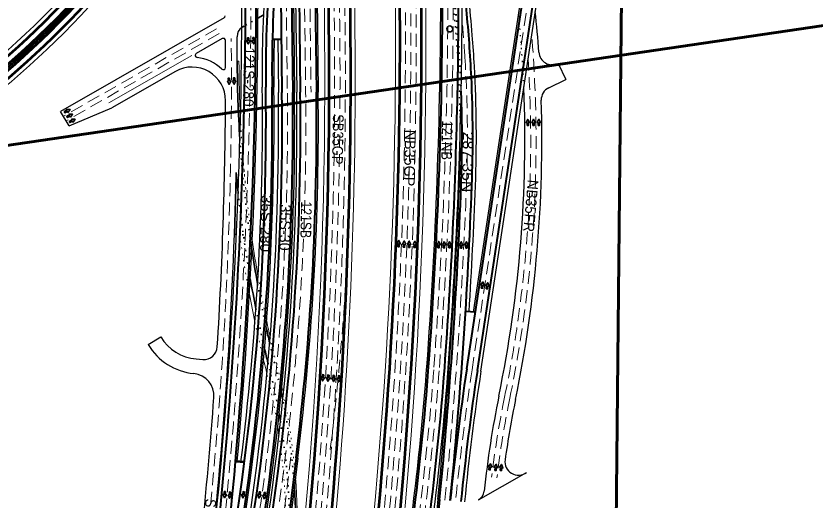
# Model space of a CAD drawing. Extents: x 2329387 to 2347382, y 6951580 to 6987999.
# Drawn here: x 2331270 to 2333058, y 6962627 to 6963710 of the extents above; entities that cross this region are included whole.
import ezdxf

# ---------------------------------------------------------------- set-up
doc = ezdxf.new("R2010")
doc.units = 0
doc.header["$LTSCALE"] = 9.6
doc.linetypes.add('DOTTED', pattern=[1.5, 0.3, -1.2])
doc.linetypes.add('MEDIUM_DASHED', pattern=[4.5, 3, -1.5])
for name, color, linetype, lineweight in [('26', 7, 'Continuous', 53), ('27', 7, 'Continuous', 40), ('28', 7, 'Continuous', 25), ('29', 7, 'DOTTED', 35), ('31', 7, 'Continuous', 53), ('41', 7, 'Continuous', 35), ('50', 7, 'MEDIUM_DASHED', 13), ('62', 7, 'Continuous', 60)]:
    doc.layers.add(name, color=color, linetype=linetype, lineweight=lineweight)
doc.layers.add('40', color=7, linetype='Continuous')

msp = doc.modelspace()

# ---------------------------------------------------------------- linework, layer by layer
at = {"layer": '26'}
for centre, radius, start, end in [((2320619.05, 6963651.709), 11510.156, 348.37024, 3.41668), ((2321018.843, 6963569.511), 11000, 348.37024, 2.99621), ((2320619.05, 6963651.709), 11558.156, 353.8091, 2.18285), ((2321018.843, 6963569.511), 10952, 352.02498, 2.27299)]:
    msp.add_arc(centre, radius, start, end, dxfattribs=at)
at = {"layer": '26', "lineweight": 13}
for centre, radius, start, end in [((2320619.05, 6963651.709), 11500.156, 348.37024, 3.35435), ((2321018.843, 6963569.511), 11010, 348.37024, 3.10741), ((2320619.05, 6963651.709), 11568.156, 353.8091, 2.18285), ((2321018.843, 6963569.511), 10942, 352.02498, 2.03298)]:
    msp.add_arc(centre, radius, start, end, dxfattribs=at)
at = {"layer": '27'}
for p, q in [((2331859.891, 6963964.924), (2331864.989, 6963538.523)), ((2331883.889, 6963965.211), (2331888.987, 6963538.81)), ((2331902.724, 6963811.829), (2331905.986, 6963539.014)), ((2331938.722, 6963812.26), (2331941.983, 6963539.444)), ((2332278.43, 6962920.203), (2332404.465, 6963752.658)), ((2332302.159, 6962916.61), (2332428.993, 6963754.341)), ((2331843.561, 6963657.847), (2331863.559, 6963658.086)), ((2332297.639, 6963047.078), (2332275.682, 6963048.447)), ((2331896.517, 6962721.31), (2331783.536, 6961807.284))]:
    msp.add_line(p, q, dxfattribs=at)
at = {"layer": '27', "lineweight": 25}
for p, q in [((2331887.889, 6963965.259), (2331892.986, 6963538.858)), ((2331894.725, 6963811.734), (2331897.986, 6963538.918)), ((2331942.721, 6963812.307), (2331945.983, 6963539.492)), ((2332293.631, 6963047.328), (2332400.51, 6963753.257)), ((2332310.069, 6962915.412), (2332436.903, 6963753.144)), ((2331855.56, 6963657.991), (2331856.989, 6963538.428)), ((2331900.487, 6962720.82), (2331787.506, 6961806.793))]:
    msp.add_line(p, q, dxfattribs=at)
at = {"layer": '27', "lineweight": 53}
msp.add_line((2331781.036, 6962711.686), (2331761.113, 6962713.441), dxfattribs=at)
at = {"layer": '27'}
for centre, radius, start, end in [((2339406.145, 6959556.474), 7976, 170.51466, 170.51466), ((2319783.502, 6963768.598), 11999.998, 350.71583, 0.79832), ((2319783.502, 6963768.598), 12023.998, 353.14789, 0.79832), ((2334658.491, 6963585.255), 2829.866, 175.42223, 180.70842), ((2334658.491, 6963585.255), 2815.866, 175.42223, 180.70842), ((2329427.098, 6963438.985), 2864.789, 4.18795, 7.21791), ((2320644.096, 6963773.403), 11580.156, 355.79715, 359.92799), ((2320644.096, 6963773.403), 11616.156, 358.83349, 359.92799), ((2329427.098, 6963438.985), 2864.789, 2.67871, 4.18794), ((2329427.098, 6963438.985), 2864.789, 357.81948, 2.67871), ((2325765.131, 6963475.29), 6064.174, 349.61744, 0.70842), ((2325765.131, 6963475.29), 6078.174, 349.61744, 0.70842), ((2325865.417, 6963466.803), 6000, 350.51466, 0.68489), ((2325865.417, 6963466.803), 6024, 350.51466, 0.68489), ((2325865.417, 6963466.803), 6041, 350.76507, 0.68489), ((2325865.417, 6963466.803), 6077, 352.95352, 0.6849), ((2320644.096, 6963773.403), 11616.156, 355.79988, 358.83349), ((2329427.098, 6963438.985), 2840.789, 357.81948, 2.00707), ((2320644.096, 6963773.403), 11630.156, 354.34987, 357.81948), ((2320644.096, 6963773.403), 11654.156, 354.34987, 357.81948), ((2326209.306, 6963364.708), 5999.959, 349.28886, 355.79988), ((2326209.306, 6963364.708), 6035.959, 349.28886, 355.79988), ((2337955.315, 6962060.73), 5741.578, 171.39088, 174.34987), ((2337955.315, 6962060.73), 5717.578, 171.39088, 174.34987), ((2337955.315, 6962060.73), 5765.578, 174.34987, 182.32731)]:
    msp.add_arc(centre, radius, start, end, dxfattribs=at)
at = {"layer": '27', "lineweight": 25}
for centre, radius, start, end in [((2319783.502, 6963768.598), 11991.998, 350.71583, 0.79832), ((2319783.502, 6963768.598), 12027.998, 354.96558, 0.79832), ((2329427.098, 6963438.985), 2872.789, 4.547, 7.97211), ((2334658.491, 6963585.255), 2837.866, 175.42223, 180.70842), ((2320644.096, 6963773.403), 11576.156, 355.79715, 359.94511), ((2320644.096, 6963773.403), 11624.156, 359.20212, 359.92799), ((2334658.491, 6963585.255), 2811.866, 178.51968, 180.70842), ((2329427.098, 6963438.985), 2872.789, 3.16532, 4.54699), ((2320644.096, 6963773.403), 11624.156, 355.79988, 359.20212), ((2329427.098, 6963438.985), 2872.789, 357.81948, 3.16532), ((2325765.131, 6963475.29), 6082.174, 349.61744, 0.70842), ((2325765.131, 6963475.29), 6056.174, 352.76318, 0.70842), ((2325865.417, 6963466.803), 5992, 350.51466, 0.68489), ((2325865.417, 6963466.803), 6028, 350.51466, 0.68489), ((2325865.417, 6963466.803), 6033, 350.76507, 0.68489), ((2325865.417, 6963466.803), 6081, 352.95352, 0.6849), ((2329427.098, 6963438.985), 2836.789, 357.81948, 0.29401), ((2320644.096, 6963773.403), 11626.156, 354.34987, 357.81948), ((2320644.096, 6963773.403), 11662.156, 356.43357, 357.81948), ((2326209.306, 6963364.708), 5995.959, 350.77341, 355.79988), ((2326209.306, 6963364.708), 6043.959, 349.28886, 355.79988), ((2337955.315, 6962060.73), 5709.578, 171.39088, 174.34987), ((2337955.315, 6962060.73), 5769.578, 174.34987, 182.32731)]:
    msp.add_arc(centre, radius, start, end, dxfattribs=at)
at = {"layer": '27', "linetype": 'DOTTED'}
msp.add_arc((2329427.098, 6963438.985), 2840.789, 2.00707, 9.24389, dxfattribs=at)
at = {"layer": '27', "linetype": 'DOTTED', "lineweight": 25}
msp.add_arc((2329427.098, 6963438.985), 2836.789, 0.29402, 8.98982, dxfattribs=at)
at = {"layer": '28', "lineweight": 35}
msp.add_line((2331823.249, 6963711.573), (2331811.33, 6963704.776), dxfattribs=at)
at = {"layer": '28'}
for p, q in [((2331735.388, 6963705.212), (2331369.146, 6963496.347)), ((2331731.057, 6963658.997), (2331673.353, 6963626.089)), ((2332482.628, 6963603.48), (2332500.38, 6963567.633)), ((2331626.602, 6963585.613), (2331484.263, 6963504.438)), ((2332462.047, 6963549.162), (2332500.38, 6963567.633)), ((2331388.592, 6963463.692), (2331369.146, 6963496.347)), ((2331388.592, 6963463.692), (2331484.263, 6963504.438)), ((2331565.734, 6962975.098), (2331594.215, 6962991.766)), ((2331672.99, 6962942.56), (2331688.11, 6962941.418)), ((2332304.35, 6962627.635), (2332411.916, 6962688.785))]:
    msp.add_line(p, q, dxfattribs=at)
at = {"layer": '28', "linetype": 'DOTTED', "lineweight": 35}
msp.add_line((2331811.33, 6963704.776), (2331780.207, 6963687.027), dxfattribs=at)
at = {"layer": '28', "lineweight": 13}
msp.add_line((2331764.819, 6963608.628), (2331768.819, 6963608.644), dxfattribs=at)
at = {"layer": '28'}
for centre, radius, start, end in [((2331732.911, 6963709.555), 5, 299.69572, 0.81201), ((2329579.73, 6963430.486), 2866.789, 3.95936, 5.79437), ((2331789.457, 6963663.522), 25, 124.76483, 180.53847), ((2331733.534, 6963654.653), 5, 0.48946, 119.69572), ((2321980.757, 6963571.336), 9784.134, 0.21838, 0.53847), ((2321980.757, 6963571.336), 9758.134, 0.13638, 0.48946), ((2331675.83, 6963621.745), 5, 119.69572, 263.20196), ((2332469.606, 6963630.507), 30, 183.95936, 295.72664), ((2331663.756, 6963520.463), 97, 46.58215, 83.20195), ((2334629.587, 6963619.547), 2864.789, 180.21838, 183.71741), ((2331663.756, 6963520.463), 75, 359.69898, 119.69572), ((2331733.862, 6963594.551), 5, 226.58215, 0.13638), ((2329579.73, 6963430.486), 2828.789, 348.36088, 2.40537), ((2332475.069, 6963522.136), 30, 115.72664, 181.81305), ((2321980.757, 6963571.336), 9758.134, 356.46392, 359.69898), ((2329579.73, 6963430.486), 2866.789, 348.36088, 1.81305), ((2321980.757, 6963571.336), 9784.134, 352.54246, 357.94854), ((2331680.521, 6963042.276), 100, 210.33806, 265.68072), ((2331680.521, 6963042.276), 133, 210.33806, 264.44438), ((2331690.369, 6962971.333), 30, 265.68072, 356.46392), ((2331662.804, 6962860.136), 50, 355.79885, 84.44438), ((2321980.757, 6963571.336), 9758.134, 352.45851, 355.79885), ((2334455.922, 6962426.078), 2149.773, 168.36088, 174.09796), ((2334455.922, 6962426.078), 2111.773, 168.36088, 172.08227), ((2332393.995, 6962712.845), 30, 172.08227, 306.68141), ((2332292.681, 6962649.744), 25, 297.82484, 354.00801)]:
    msp.add_arc(centre, radius, start, end, dxfattribs=at)
at = {"layer": '28', "linetype": 'DOTTED'}
for centre, radius, start, end in [((2329579.73, 6963430.486), 2828.789, 2.40537, 5.72863), ((2334629.587, 6963619.547), 2864.789, 183.71741, 185.54829)]:
    msp.add_arc(centre, radius, start, end, dxfattribs=at)
at = {"layer": '28', "lineweight": 13}
for centre, radius, start, end in [((2334629.587, 6963619.547), 2860.789, 180.21835, 182.74682), ((2334629.587, 6963619.547), 2860.789, 188.25774, 189.89333), ((2334629.587, 6963619.547), 2886.789, 190.61635, 191.87502), ((2334629.587, 6963619.547), 2860.789, 191.94861, 192.67825), ((2334629.587, 6963619.547), 2886.789, 193.6017, 194.06553), ((2330382.082, 6962555.363), 1491.999, 13.73046, 14.06553), ((2330382.082, 6962555.363), 1517.999, 11.74962, 12.3699), ((2330382.082, 6962555.363), 1491.999, 8.34815, 9.07887), ((2330382.082, 6962555.363), 1517.999, 353.8183, 4.62003)]:
    msp.add_arc(centre, radius, start, end, dxfattribs=at)
at = {"layer": '28', "linetype": 'DOTTED', "lineweight": 13}
for centre, radius, start, end in [((2334629.587, 6963619.547), 2860.789, 182.74682, 188.25774), ((2334629.587, 6963619.547), 2886.789, 187.94221, 190.61635), ((2334629.587, 6963619.547), 2860.789, 189.89333, 191.94861), ((2334629.587, 6963619.547), 2886.789, 191.87502, 193.6017), ((2334629.587, 6963619.547), 2860.789, 192.67825, 194.06553), ((2330382.082, 6962555.363), 1517.999, 12.3699, 14.06553), ((2330382.082, 6962555.363), 1491.999, 9.07887, 13.73046), ((2330382.082, 6962555.363), 1517.999, 4.62003, 11.74962), ((2330382.082, 6962555.363), 1491.999, 357.81169, 8.34815)]:
    msp.add_arc(centre, radius, start, end, dxfattribs=at)
at = {"layer": '29'}
for p, q in [((2331780.207, 6963687.027), (2331777.072, 6963685.239)), ((2331778.607, 6963220.376), (2331762.988, 6963220.936))]:
    msp.add_line(p, q, dxfattribs=at)
at = {"layer": '29', "linetype": 'Continuous'}
msp.add_line((2331762.988, 6963220.936), (2331758.619, 6963221.092), dxfattribs=at)
at = {"layer": '29'}
for centre, radius, start, end in [((2331789.457, 6963663.522), 25, 119.69572, 124.76483), ((2334629.587, 6963619.547), 2864.789, 183.71739, 188.66291), ((2334629.587, 6963619.547), 2878.789, 186.06786, 189.95134), ((2334629.587, 6963619.547), 2864.789, 190.22859, 192.21722), ((2334629.587, 6963619.547), 2878.789, 191.3098, 193.12052), ((2334629.587, 6963619.547), 2864.789, 192.93344, 194.06553), ((2334629.587, 6963619.547), 2878.789, 193.78065, 194.06553), ((2330382.082, 6962555.363), 1513.999, 11.89833, 14.06553), ((2330382.082, 6962555.363), 1499.999, 10.15303, 14.06553), ((2330382.082, 6962555.363), 1513.999, 3.86264, 11.26427), ((2330382.082, 6962555.363), 1499.999, 0.60632, 9.46235)]:
    msp.add_arc(centre, radius, start, end, dxfattribs=at)
at = {"layer": '29', "linetype": 'Continuous'}
for centre, radius, start, end in [((2334629.587, 6963619.547), 2864.789, 180.21835, 183.71739), ((2321980.757, 6963571.336), 9784.134, 357.94854, 358.75788), ((2334629.587, 6963619.547), 2878.789, 185.18787, 185.29222), ((2334629.587, 6963619.547), 2878.789, 185.18786, 186.06786), ((2334629.587, 6963619.547), 2864.789, 188.66292, 190.22859), ((2334629.587, 6963619.547), 2878.789, 189.95135, 191.3098), ((2334629.587, 6963619.547), 2864.789, 192.21722, 192.93344), ((2334629.587, 6963619.547), 2878.789, 193.12052, 193.78065), ((2330382.082, 6962555.363), 1513.999, 11.26427, 11.89833), ((2330382.082, 6962555.363), 1499.999, 9.46235, 10.15303), ((2330382.082, 6962555.363), 1513.999, 353.8183, 3.86264)]:
    msp.add_arc(centre, radius, start, end, dxfattribs=at)
at = {"layer": '31', "lineweight": 13}
for radius, end in [(2054.483, 348.49858), (2082.483, 347.70072), (2084.483, 347.64774), (2112.483, 346.95514)]:
    msp.add_arc((2329883.662, 6965166.203), radius, 300.39505, end, dxfattribs=at)
at = {"layer": '31'}
for radius, end in [(2064.483, 348.20098), (2078.483, 347.80819), (2088.483, 347.54327), (2102.483, 347.19243)]:
    msp.add_arc((2329883.662, 6965166.203), radius, 300.39505, end, dxfattribs=at)
at = {"layer": '41'}
for points in [[(2331790.891, 6963661.054), (2331787.892, 6963660.956), (2331788.114, 6963654.153), (2331785.678, 6963654.074), (2331789.69, 6963647.001), (2331793.232, 6963654.32), (2331791.113, 6963654.251)], [(2331803.026, 6963661.337), (2331800.027, 6963661.239), (2331800.249, 6963654.436), (2331797.813, 6963654.356), (2331801.825, 6963647.283), (2331805.367, 6963654.603), (2331803.248, 6963654.534)], [(2331747.951, 6963570.808), (2331744.951, 6963570.71), (2331745.174, 6963563.907), (2331742.737, 6963563.827), (2331746.749, 6963556.754), (2331750.291, 6963564.074), (2331748.173, 6963564.004)], [(2331759.264, 6963571.071), (2331756.265, 6963570.973), (2331756.487, 6963564.17), (2331754.051, 6963564.091), (2331758.062, 6963557.018), (2331761.604, 6963564.337), (2331759.486, 6963564.268)], [(2331377.597, 6963496.027), (2331378.906, 6963493.327), (2331385.031, 6963496.296), (2331386.095, 6963494.103), (2331390.925, 6963500.645), (2331382.797, 6963500.904), (2331383.722, 6963498.996)], [(2331383.314, 6963485.285), (2331384.623, 6963482.585), (2331390.748, 6963485.555), (2331391.811, 6963483.361), (2331396.641, 6963489.903), (2331388.514, 6963490.162), (2331389.438, 6963488.255)], [(2331388.918, 6963473.904), (2331390.227, 6963471.204), (2331396.352, 6963474.174), (2331397.415, 6963471.98), (2331402.245, 6963478.522), (2331394.118, 6963478.781), (2331395.042, 6963476.874)], [(2332413.321, 6963464.425), (2332416.321, 6963464.431), (2332416.307, 6963471.238), (2332418.744, 6963471.243), (2332414.95, 6963478.435), (2332411.187, 6963471.227), (2332413.306, 6963471.232)], [(2332426.006, 6963464.529), (2332429.007, 6963464.535), (2332428.992, 6963471.342), (2332431.43, 6963471.347), (2332427.636, 6963478.539), (2332423.872, 6963471.331), (2332425.992, 6963471.335)], [(2332438.224, 6963464.729), (2332441.225, 6963464.736), (2332441.211, 6963471.542), (2332443.648, 6963471.548), (2332439.854, 6963478.74), (2332436.09, 6963471.532), (2332438.21, 6963471.536)], [(2332124.457, 6963193.624), (2332127.456, 6963193.541), (2332127.646, 6963200.345), (2332130.082, 6963200.277), (2332126.505, 6963207.58), (2332122.527, 6963200.487), (2332124.646, 6963200.428)], [(2332136.489, 6963192.561), (2332139.488, 6963192.477), (2332139.678, 6963199.281), (2332142.114, 6963199.214), (2332138.537, 6963206.516), (2332134.559, 6963199.424), (2332136.678, 6963199.365)], [(2332147.797, 6963192.14), (2332150.797, 6963192.057), (2332150.986, 6963198.861), (2332153.423, 6963198.793), (2332149.845, 6963206.096), (2332145.868, 6963199.003), (2332147.987, 6963198.945)], [(2332160.367, 6963191.834), (2332163.367, 6963191.751), (2332163.556, 6963198.555), (2332165.992, 6963198.487), (2332162.415, 6963205.789), (2332158.438, 6963198.697), (2332160.556, 6963198.638)], [(2332213.987, 6963191.388), (2332216.988, 6963191.374), (2332217.019, 6963198.181), (2332219.456, 6963198.169), (2332215.711, 6963205.387), (2332211.899, 6963198.204), (2332214.018, 6963198.194)], [(2332225.968, 6963190.81), (2332228.969, 6963190.796), (2332229, 6963197.602), (2332231.438, 6963197.591), (2332227.692, 6963204.809), (2332223.88, 6963197.626), (2332226, 6963197.616)], [(2332238.106, 6963190.864), (2332241.107, 6963190.85), (2332241.138, 6963197.657), (2332243.575, 6963197.645), (2332239.83, 6963204.863), (2332236.018, 6963197.68), (2332238.137, 6963197.67)], [(2332264.212, 6963190.637), (2332267.213, 6963190.623), (2332267.244, 6963197.43), (2332269.682, 6963197.418), (2332265.936, 6963204.636), (2332262.124, 6963197.453), (2332264.244, 6963197.444)], [(2332276.35, 6963190.691), (2332279.35, 6963190.677), (2332279.382, 6963197.484), (2332281.819, 6963197.472), (2332278.074, 6963204.69), (2332274.262, 6963197.507), (2332276.381, 6963197.498)], [(2332310.718, 6963101.297), (2332313.677, 6963100.798), (2332314.81, 6963107.509), (2332317.213, 6963107.104), (2332314.685, 6963114.832), (2332309.761, 6963108.361), (2332311.851, 6963108.009)], [(2332321.516, 6963099.46), (2332324.475, 6963098.961), (2332325.607, 6963105.672), (2332328.011, 6963105.267), (2332325.483, 6963112.995), (2332320.559, 6963106.524), (2332322.648, 6963106.172)], [(2331958.338, 6962907.47), (2331955.341, 6962907.621), (2331954.998, 6962900.823), (2331952.564, 6962900.946), (2331955.975, 6962893.564), (2331960.112, 6962900.565), (2331957.995, 6962900.672)], [(2331970.315, 6962906.73), (2331967.318, 6962906.881), (2331966.975, 6962900.083), (2331964.541, 6962900.205), (2331967.952, 6962892.824), (2331972.089, 6962899.825), (2331969.972, 6962899.932)], [(2331982.292, 6962905.989), (2331979.295, 6962906.141), (2331978.952, 6962899.342), (2331976.518, 6962899.465), (2331979.93, 6962892.084), (2331984.066, 6962899.085), (2331981.949, 6962899.191)], [(2331994.269, 6962905.249), (2331991.272, 6962905.4), (2331990.93, 6962898.602), (2331988.495, 6962898.725), (2331991.907, 6962891.344), (2331996.043, 6962898.344), (2331993.927, 6962898.451)], [(2332328.001, 6962694.82), (2332330.972, 6962694.405), (2332331.915, 6962701.146), (2332334.328, 6962700.809), (2332331.583, 6962708.463), (2332326.844, 6962701.855), (2332328.943, 6962701.562)], [(2332340.907, 6962693.485), (2332343.879, 6962693.069), (2332344.821, 6962699.811), (2332347.235, 6962699.473), (2332344.489, 6962707.127), (2332339.75, 6962700.519), (2332341.85, 6962700.226)], [(2332352.924, 6962693.04), (2332355.896, 6962692.624), (2332356.838, 6962699.365), (2332359.252, 6962699.028), (2332356.506, 6962706.682), (2332351.767, 6962700.074), (2332353.866, 6962699.781)], [(2331738.885, 6962645.963), (2331735.891, 6962646.163), (2331735.438, 6962639.372), (2331733.006, 6962639.534), (2331736.296, 6962632.098), (2331740.546, 6962639.03), (2331738.432, 6962639.171)], [(2331750.52, 6962644.951), (2331747.526, 6962645.151), (2331747.072, 6962638.36), (2331744.64, 6962638.522), (2331747.93, 6962631.086), (2331752.181, 6962638.018), (2331750.066, 6962638.159)], [(2331780.891, 6962645.715), (2331777.915, 6962646.098), (2331777.046, 6962639.347), (2331774.629, 6962639.658), (2331777.457, 6962632.035), (2331782.125, 6962638.694), (2331780.022, 6962638.964)], [(2331816.978, 6962645.27), (2331814.002, 6962645.654), (2331813.132, 6962638.903), (2331810.715, 6962639.215), (2331813.542, 6962631.591), (2331818.211, 6962638.249), (2331816.108, 6962638.52)], [(2331828.386, 6962643.649), (2331825.41, 6962644.032), (2331824.54, 6962637.281), (2331822.123, 6962637.593), (2331824.95, 6962629.969), (2331829.618, 6962636.627), (2331827.516, 6962636.898)]]:
    msp.add_lwpolyline(points, close=True, dxfattribs=at)
at = {"layer": '50'}
for p, q in [((2331871.89, 6963965.067), (2331876.988, 6963538.667)), ((2331914.723, 6963811.973), (2331917.985, 6963539.157)), ((2331926.723, 6963812.116), (2331929.984, 6963539.301)), ((2332290.295, 6962918.406), (2332416.33, 6963750.862)), ((2331718.672, 6963680.714), (2331376.207, 6963485.409)), ((2331724.617, 6963670.29), (2331382.152, 6963474.985)), ((2331884.608, 6962722.782), (2331771.627, 6961808.756))]:
    msp.add_line(p, q, dxfattribs=at)
at = {"layer": '50', "linetype": 'Continuous'}
msp.add_line((2331663.342, 6963621.53), (2331477.823, 6963515.731), dxfattribs=at)
at = {"layer": '50', "linetype": 'DOTTED'}
msp.add_line((2331780.994, 6963355.668), (2331786.908, 6963291.834), dxfattribs=at)
at = {"layer": '50', "linetype": 'Continuous', "lineweight": 35}
msp.add_circle((2332240.47, 6963680.652), 6.657, dxfattribs=at)
at = {"layer": '50'}
for centre, radius, start, end in [((2320619.05, 6963651.709), 11546.156, 348.37024, 3.62206), ((2320619.05, 6963651.709), 11522.156, 348.37024, 3.48829), ((2320619.05, 6963651.709), 11534.156, 348.37024, 3.55667), ((2321018.843, 6963569.511), 10988, 348.34293, 2.85027), ((2321018.843, 6963569.511), 10976, 348.37024, 2.68674), ((2321018.843, 6963569.511), 10964, 348.37024, 2.49877), ((2319783.502, 6963768.598), 12011.998, 350.71583, 0.79832), ((2320644.096, 6963773.403), 11592.156, 355.79988, 359.92799), ((2320644.096, 6963773.403), 11604.156, 355.79988, 359.92799), ((2329427.098, 6963438.985), 2852.789, 3.58835, 5.22937), ((2321980.757, 6963571.336), 9771.134, 352.6223, 0.51494), ((2329579.73, 6963430.486), 2853.789, 348.36088, 4.74029), ((2329427.098, 6963438.985), 2852.789, 357.81948, 3.58835), ((2329579.73, 6963430.486), 2841.789, 348.36088, 3.67929), ((2325953.916, 6963483.926), 6065, 352.95352, 0.6849), ((2325865.417, 6963466.803), 6012, 350.51466, 0.68489), ((2325865.417, 6963466.803), 6053, 350.76507, 0.68489), ((2320644.096, 6963773.403), 11642.156, 354.34987, 357.81948), ((2326209.306, 6963364.708), 6011.959, 349.28886, 355.79988), ((2326209.306, 6963364.708), 6023.959, 349.28886, 355.79988), ((2337955.315, 6962060.73), 5729.578, 171.39088, 174.34987), ((2334455.922, 6962426.078), 2136.773, 168.36088, 173.22823), ((2334455.922, 6962426.078), 2124.773, 168.36088, 173.22823)]:
    msp.add_arc(centre, radius, start, end, dxfattribs=at)
at = {"layer": '50', "linetype": 'DOTTED'}
msp.add_arc((2334629.587, 6963619.547), 2860.789, 184.8375, 185.29249, dxfattribs=at)
at = {"layer": '62'}
for points in [[(2338114.665, 6964428.225), (2329704.893, 6963193.017), (2329428.787, 6965072.851), (2337838.559, 6966308.058)], [(2332642.295, 6965522.154), (2332560.849, 6957416.973), (2330660.943, 6957436.065), (2330739.467, 6965250.394)]]:
    msp.add_lwpolyline(points, close=True, dxfattribs=at)

# ---------------------------------------------------------------- texts
at = {"layer": '40'}
for s, rotation, width, p in [('121S-280', 268.862, 0.95, (2331780.282, 6963639.489)), ('SB35GP', 268.862, 0.9, (2331979.194, 6963490.25)), ('121NB', 268.862, 0.9, (2332223.186, 6963476.077)), ('287-35N', 268.862, 1.1, (2332270.163, 6963450.92)), ('NB35FR', 264.862, 0.95, (2332415.217, 6963344.242)), ('35S-280', 268.581, 1.05, (2331818.898, 6963309.385)), ('121SB', 268.862, 0.85, (2331907.808, 6963294.98)), ('SB35FR', 264.862, 0.9, (2331694.163, 6962630.81))]:
    msp.add_text(s, height=24, rotation=rotation, dxfattribs=dict(at, width=width)).set_placement(p)
for s, p in [('NB35GP', (2332140.328, 6963455.604)), ('35S-30', (2331861.041, 6963288.568))]:
    msp.add_text(s, height=24, rotation=268.862, dxfattribs=at).set_placement(p)

doc.saveas('drawing.dxf')
